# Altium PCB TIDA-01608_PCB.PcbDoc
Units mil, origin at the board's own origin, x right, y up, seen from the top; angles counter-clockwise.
Board outline 3040 x 2040 mil, 2 copper layers (Top Layer, Bottom Layer), stack 62 mil thick; 66 components, 23 nets, 147 pads, 82 vias.
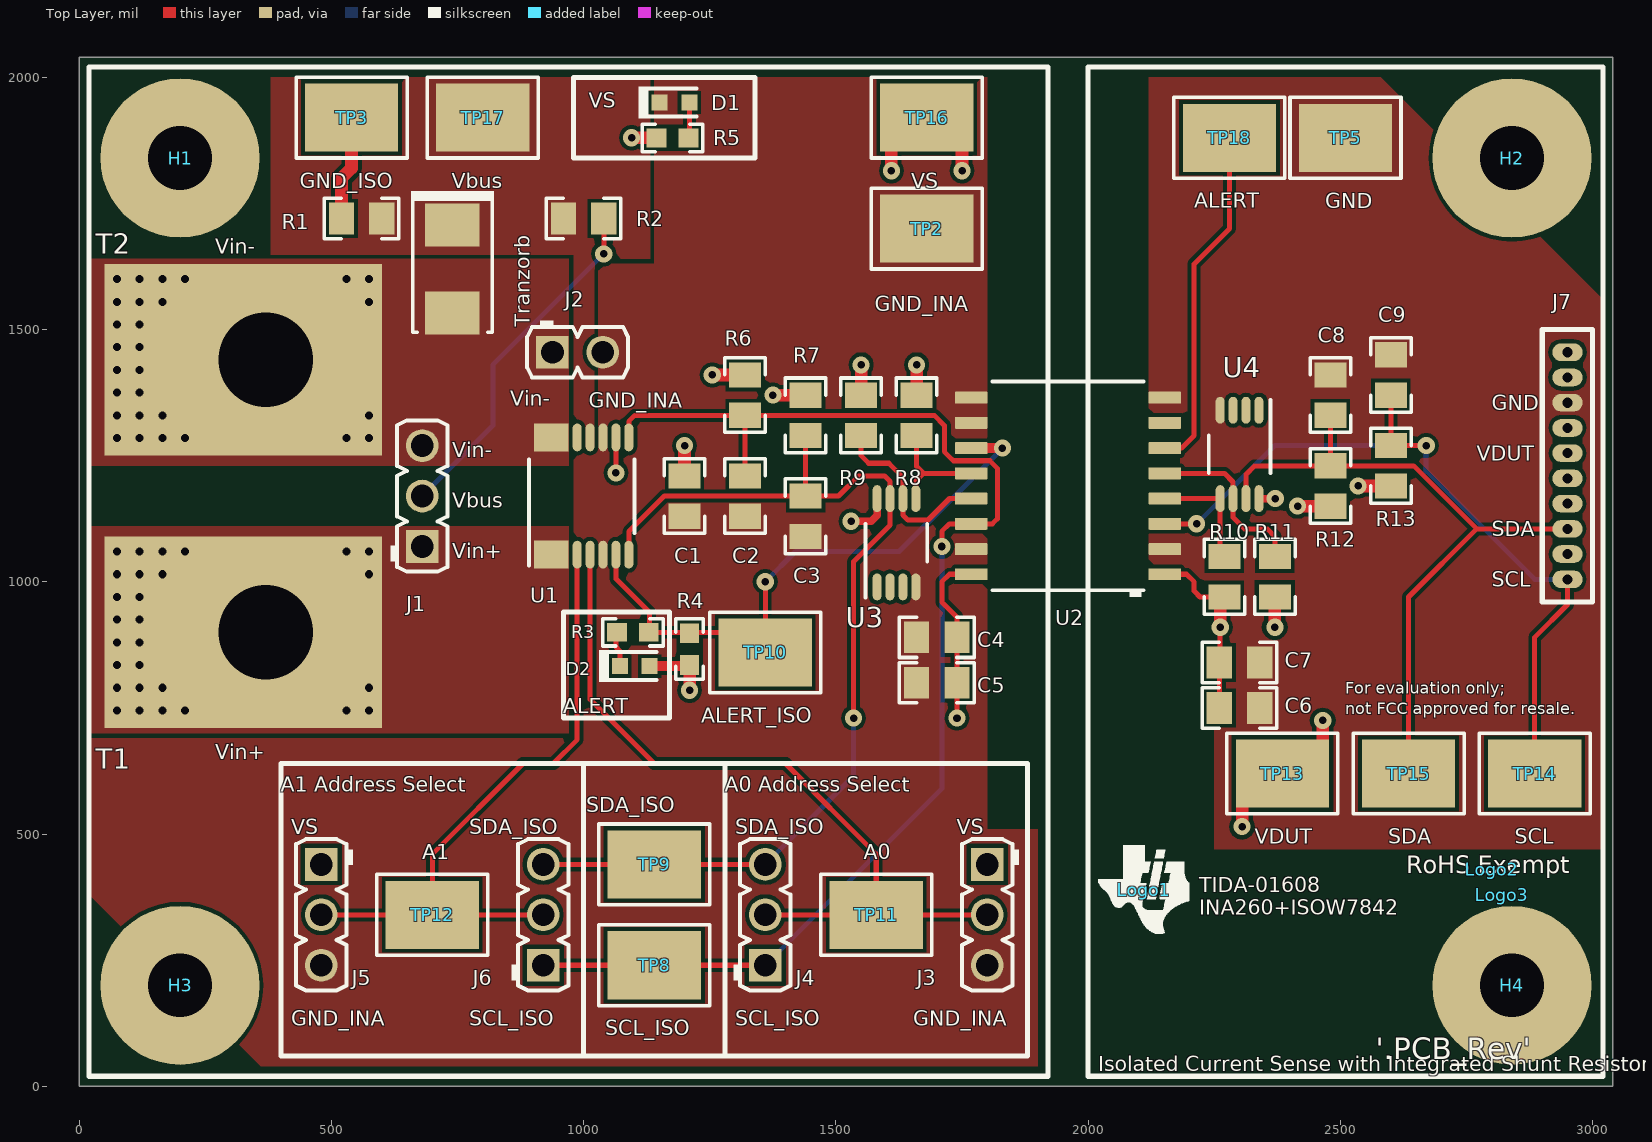
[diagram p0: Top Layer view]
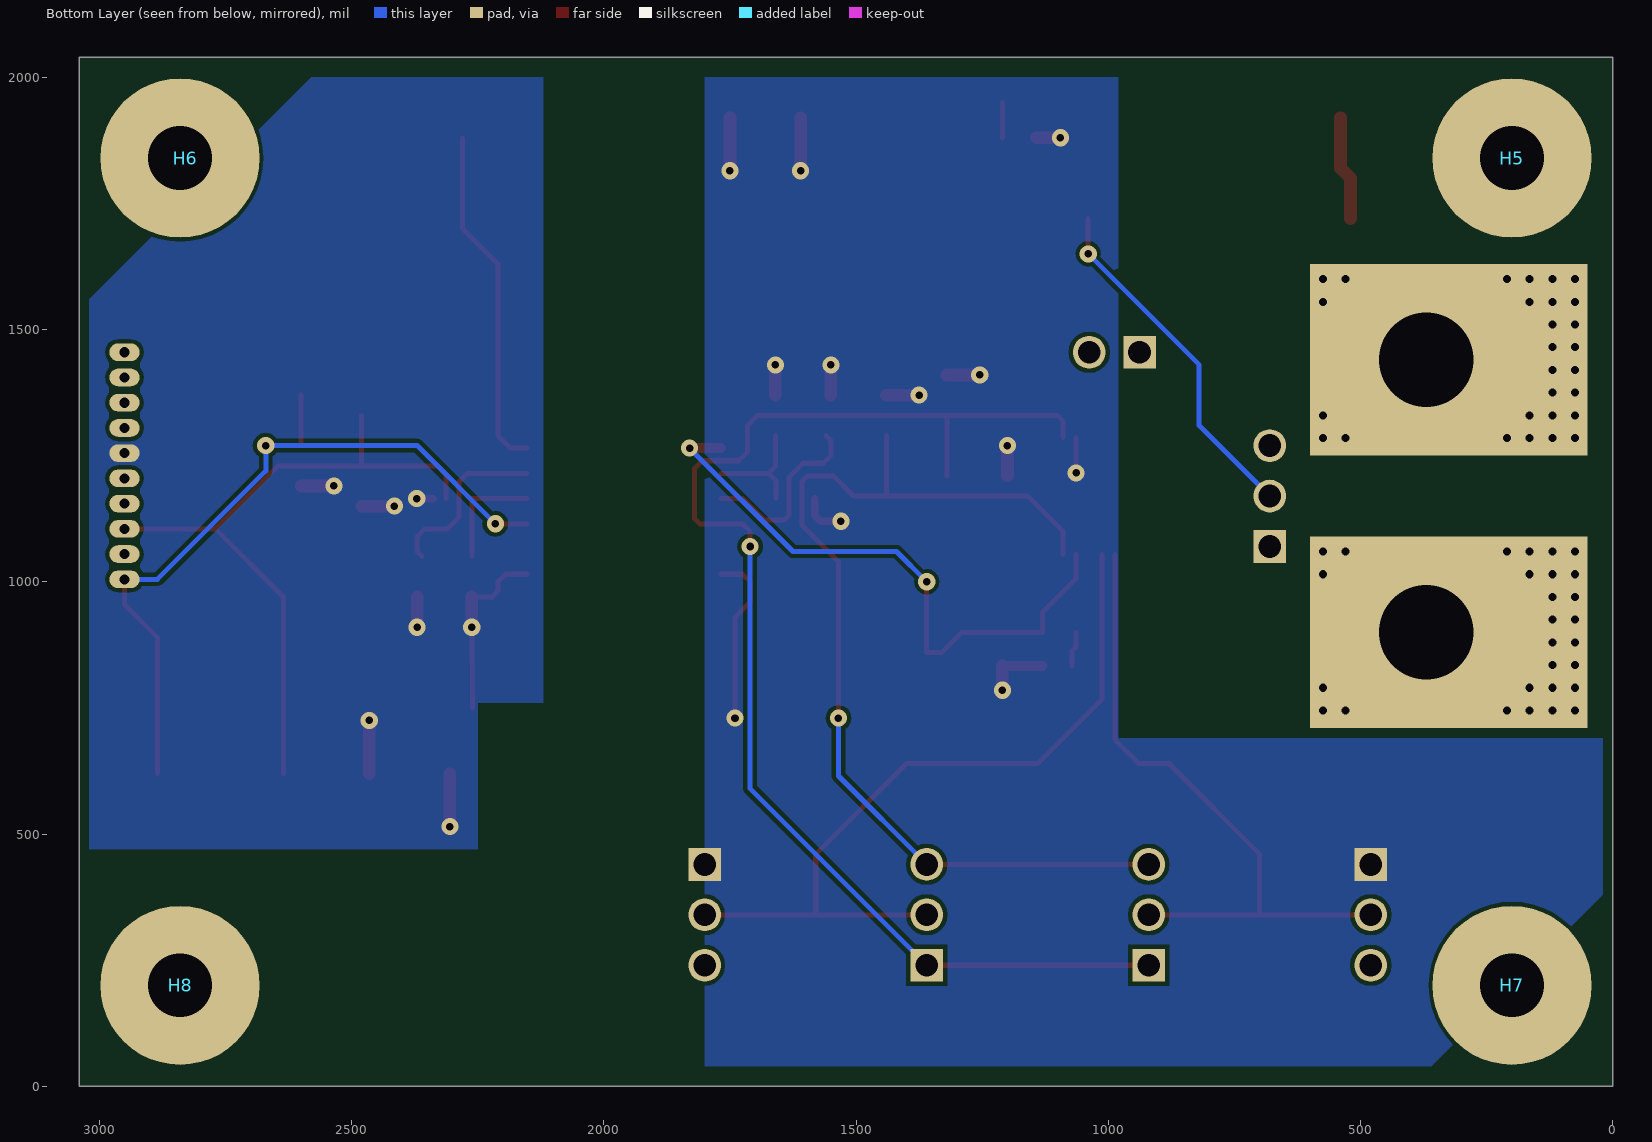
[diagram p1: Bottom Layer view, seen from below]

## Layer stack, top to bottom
Top Solder: solder mask 0.4, Solder Resist, Dk 3.5
Top Layer: signal copper 1.4
Dielectric1: core 59.2, FR-4, Dk 4.8
Bottom Layer: signal copper 1.4
Bottom Solder: solder mask 0.4, Solder Resist, Dk 3.5

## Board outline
0,0 0,2040 3040,2040 3040,0

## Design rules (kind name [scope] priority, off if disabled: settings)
AcuteAngle [All] p1: minimum=4.50000000000000E+0001 checktracksonly=FALSE
AssemblyTestPointUsage [All] p1: valid=2
Clearance Clearance_Keepouts [((IsTrack Or IsArc) And Not InPoly) And IsFree and IsKeepOut vs ((IsTrack Or IsArc) And Not InPoly) And IsFree and IsKeepOut] p1: gap=0 ignorepadtopadclearanceinfootprint=FALSE
Clearance Clearance_BoardEdge_MountingHoles [OnCopper and InComponentClass('Mounting Holes') vs IsKeepOut] p2: gap=40 ignorepadtopadclearanceinfootprint=FALSE except(0: Arc-Hole Track-Hole SMDPad-Hole THPad-Hole Via-Hole Fill-Hole Poly-Hole Region-Hole Text-Hole)
Clearance Clearance_BoardEdge_Poly [OnCopper and InPoly vs IsKeepOut] p3: gap=25 ignorepadtopadclearanceinfootprint=FALSE except(0: Arc-Hole Track-Hole SMDPad-Hole THPad-Hole Via-Hole Fill-Hole Poly-Hole Region-Hole Text-Hole)
Clearance Clearance_BoardEdge [OnCopper and Not InComponentClass('Logo') and not InComponentClass('FiducialMark') and not InRegion(1000,500,4000,800) and Not IsKeepout vs IsKeepOut] p4: gap=20 ignorepadtopadclearanceinfootprint=FALSE except(0: Arc-Hole Track-Hole SMDPad-Hole THPad-Hole Via-Hole Fill-Hole Poly-Hole Region-Hole Text-Hole)
Clearance Clearance_Poly [InPolygon] p5: gap=8 ignorepadtopadclearanceinfootprint=FALSE except(0: Arc-Hole Track-Hole SMDPad-Hole THPad-Hole Via-Hole Fill-Hole Poly-Hole Region-Hole Text-Hole)
Clearance [All] p6: gap=7 ignorepadtopadclearanceinfootprint=FALSE except(0: Arc-Hole Track-Hole SMDPad-Hole THPad-Hole Via-Hole Fill-Hole Poly-Hole Region-Hole Text-Hole)
ComponentClearance ComponentClearance_FCCLogo [InComponent('Logo3') vs InComponent('H4')] p1: gap=0 collisioncheckmode=3 verticalgap=0 showdistances=FALSE
ComponentClearance ComponentClearance_MountingHoles_FiducialMarks [InComponentClass('Mounting Holes') vs InComponentClass('FiducialMark')] p2: gap=7 collisioncheckmode=3 verticalgap=10 showdistances=FALSE
ComponentClearance ComponentClearance_Shunt [InComponentClass('Header') vs InComponentClass('Shunt')] p3: gap=0 collisioncheckmode=3 verticalgap=0 showdistances=FALSE
ComponentClearance ComponentClearance_Logo [InComponentClass('Logo')] p4: gap=0 collisioncheckmode=3 verticalgap=0 showdistances=FALSE
ComponentClearance ComponentClearance_ScrewToNut [(HasFootprint('NY PMS 440 0025 PH')) vs (HasFootprint('Keystone_1902C'))] p5: gap=5 collisioncheckmode=3 verticalgap=10 showdistances=FALSE
ComponentClearance ComponentClearance_MountingHoles [InComponentClass('Mounting Holes') vs InAnyComponent And Not InComponentClass('Hardware')] p6: gap=10 collisioncheckmode=3 verticalgap=10 showdistances=TRUE
ComponentClearance ComponentClearance_SmallPassives [HasFootprint('0201*') or HasFootprint('0402*') or HasFootprint('0508') or HasFootprint('0603*') or HasFootprint('0612') or HasFootprint('0805*') or HasFootprint('0815*') or HasFootprint('0830*') or HasFootprint('1206*') or HasFootprint('1210*') or HasFootprint('1808*') or HasFootprint('1812*') or HasFootprint('1825*') or HasFootprint('2010*') or HasFootprint('2220*') or HasFootprint('2225*') or HasFootprint('2512*') or HasFootprint('2728*') or HasFootprint('3518*') vs HasFootprint('0201*') or HasFootprint('0402*') or HasFootprint('0508') or HasFootprint('0603*') or HasFootprint('0612') or HasFootprint('0805*') or HasFootprint('0815*') or HasFootprint('0830*') or HasFootprint('1206*') or HasFootprint('1210*') or HasFootprint('1808*') or HasFootprint('1812*') or HasFootprint('1825*') or HasFootprint('2010*') or HasFootprint('2220*') or HasFootprint('2225*') or HasFootprint('2512*') or HasFootprint('2728*') or HasFootprint('3518*')] p7: gap=20 collisioncheckmode=3 verticalgap=10 showdistances=FALSE
ComponentClearance ComponentClearance_THtoSMT [IsThruComponent And  Not InComponentClass('Hardware') vs IsSMTComponent And  Not InComponentClass('Hardware')] p8: gap=10 collisioncheckmode=3 verticalgap=10 showdistances=FALSE
ComponentClearance ComponentClearance_THtoTH [IsThruComponent vs IsThruComponent] p9: gap=10 collisioncheckmode=3 verticalgap=10 showdistances=FALSE
ComponentClearance [Not InComponentClass('Hardware') And  Not InComponentClass('Logo') vs Not InComponentClass('Hardware') And  Not InComponentClass('Logo')] p10: gap=7 collisioncheckmode=3 verticalgap=7 showdistances=TRUE
DiffPairsRouting [All] p1: maxlimit=100 minlimit=10 mostfreqgap=10 toplayer_minwidth=15 toplayer_maxwidth=15 toplayer_prefwidth=15 bottomlayer_minwidth=15 bottomlayer_maxwidth=15 bottomlayer_prefwidth=15 maxuncoupledlength=1000
FabricationTestPointUsage TestPointUsage [All] p1: valid=2 allowmultiple=FALSE
FabricationTestpoint Testpoint [All] p1: side=3 testpointundercomponent=TRUE minsize=40 maxsize=100 preferedsize=60 minholesize=0 maxholesize=40 preferedholesize=32 testpointgrid=1 allowsidetop=TRUE allowsidebottom=TRUE usegrid=TRUE gridtolerance=0.01
FanoutControl Fanout_LCC [IsLCC] p1: bgadir=Out bgaviamode=Centered fanoutstyle=Auto fanoutdirection=Alternating viagrid=1 // Fanout_LCC (Default Rule)
FanoutControl Fanout_BGA [IsBGA] p2: bgadir=Out bgaviamode=Centered fanoutstyle=Auto fanoutdirection=Alternating viagrid=1 // Fanout_BGA (Default Rule)
FanoutControl Fanout_Default [All] p4: bgadir=Out bgaviamode=Centered fanoutstyle=Auto fanoutdirection=Alternating viagrid=1 // Fanout_Default (Default Rule)
FanoutControl Fanout_Small [(CompPinCount < 5)] p5: bgadir=Out bgaviamode=Centered fanoutstyle=Auto fanoutdirection=OutThenIn viagrid=1 // Fanout_Small (Default Rule)
Height [All] p1 off: minheight=0 maxheight=1000 prefheight=500
HoleSize [All] p1: absolutevalues=TRUE maxlimit=251 minlimit=8 maxpercent=80.000 minpercent=20.000
MinimumAnnularRing MinimumAnnularRing_ThermalPadVias [IsVia and InAnyComponent] p1: minimumring=5.91
MinimumAnnularRing [All] p2: minimumring=7
MinimumSolderMaskSliver MinimumSolderMaskSliver_Logo [InComponentClass('Logo') vs InComponentClass('Logo')] p1: minsoldermaskwidth=0.7
MinimumSolderMaskSliver [All] p2: minsoldermaskwidth=4
PlaneConnect [All] p1: planeconnectstyle=Relief reliefexpansion=10 reliefentries=4 reliefconductorwidth=10 reliefairgap=10
PolygonConnect [All] p1: connectstyle=Direct reliefconductorwidth=10 reliefentries=4 polygonreliefangle="90 Angle" airgapwidth=10
RoutingVias ThermalPadVias [IsVia and InAnyComponent] p1: holewidth=8 width=19.68 viastyle="Through Hole" minholewidth=7.87 minwidth=19.68 maxholewidth=999 maxwidth=999
RoutingVias [All] p2: holewidth=15 width=34 viastyle="Through Hole" minholewidth=8 minwidth=26 maxholewidth=999 maxwidth=999
SilkToSilkClearance SilkToSilkClearance_Pb-FreeLogo [(HasFootprint('Pb-Free_Overlay_Medium') OR HasFootprint('Pb-Free_Overlay_Small')) vs (HasFootprint('Pb-Free_Overlay_Medium') OR HasFootprint('Pb-Free_Overlay_Small'))] p1 off: silktosilkclearance=0
SilkToSilkClearance [All] p2 off: silktosilkclearance=3
SilkToSolderMaskClearance SilkToComonentPadClearance [IsPad and InAnycomponent vs Not InComponentClass('Hardware')] p1: minsilkscreentomaskgap=3 clearancetoexposedcopper=TRUE
SilkToSolderMaskClearance "Silk to Solder Mask Opening" [Not InComponentClass('Hardware') vs Not InComponentClass('Hardware')] p2: minsilkscreentomaskgap=3 clearancetoexposedcopper=FALSE
SolderMaskExpansion [All] p1: expansion=0
Width [All] p1: maxlimit=100 minlimit=6 preferedwidth=10 checkconnectedcopper=TRUE
15 further rules are at their usual default settings.

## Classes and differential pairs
component class AssemblyNote: ZZ2 ZZ3 ZZ4
component class Header: J1 J2 J3 J4 J5 J6
component class TIDA-01608_SCH: C1 C2 C3 C4 C5 C6 C7 C8 C9 D1 D2 D3 J1 J2 J3 J4 J5 J6 J7 R1 R2 R3 R4 R5 R6 R7 R8 R9 R10 R11 R12 R13 T1 T2 TP2 TP3 TP5 TP8 TP9 TP10 TP11 TP12 TP13 TP14 TP15 TP16 TP17 TP18 Tranzorb U1 U2 U3 U4
component class "Mounting Holes": H1 H2 H3 H4
component class Logo: Logo1
component class TIDA-01608_HW: H1 H2 H3 H4 H5 H6 H7 H8 Logo1 Logo2 Logo3 ZZ2 ZZ3 ZZ4

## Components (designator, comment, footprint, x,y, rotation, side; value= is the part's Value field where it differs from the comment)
C1 "08055C104KAT2A" 0805_HV 1200,1170 r270 top value=0.1uF
C2 "08051A330JAT2A" 0805_HV 1320,1170 r270 top value=33pF
C3 "08051A330JAT2A" 0805_HV 1440,1130 r270 top value=33pF
C4 "GRM21BR61A226ME44L" 0805_HV 1700,890 r0 top value=22uF
C5 "08055C104KAT2A" 0805_HV 1700,800 r180 top value=0.1uF
C6 "08055C104KAT2A" 0805_HV 2300,750 r0 top value=0.1uF
C7 "GRM21BR61A226ME44L" 0805_HV 2300,840 r180 top value=22uF
C8 "08051A330JAT2A" 0805_HV 2480,1370 r90 top value=33pF
C9 "08051A330JAT2A" 0805_HV 2600,1410 r90 top value=33pF
D1 "LTST-C190GKT" LED_LTST-C190 1180,1950 r180 top value=Green
D2 "LTST-C190CKT" LED_LTST-C190_Red 1101.38,833.07 r180 top value=Red
H1 "NY PMS 440 0025 PH" "NY PMS 440 0025 PH"#1 200,1840 r0 top locked
H2 "NY PMS 440 0025 PH" "NY PMS 440 0025 PH"#2 2830,1840 r0 top locked
H3 "NY PMS 440 0025 PH" "NY PMS 440 0025 PH"#1 200,200 r0 top locked
H4 "NY PMS 440 0025 PH" "NY PMS 440 0025 PH"#1 2840,200 r0 top locked
H5 "1902C" Keystone_1902C 200,1840 r180 bottom locked
H6 "1902C" Keystone_1902C 2830,1840 r180 bottom locked
H7 "1902C" Keystone_1902C 200,200 r180 bottom locked
H8 "1902C" Keystone_1902C 2840,200 r180 bottom locked
J1 "61300311121" WURTH_61300311121 680,1170 r90 top
J2 "61300211121" WURTH_61300211121 988,1455 r0 top
J3 "61300311121" WURTH_61300311121 1800,340 r270 top
J4 "61300311121" WURTH_61300311121 1360,340 r90 top
J5 "61300311121" WURTH_61300311121 480,340 r270 top
J6 "61300311121" WURTH_61300311121 920,340 r90 top
J7 "851-43-010-20-001000" 851-43-010-20-001000 2950,1230 r180 top
Logo1 "Texas Instruments" TI_Symbol_Overlay_Small 2110,390 r0 top
Logo2 "EU RoHS Exempt Logo" EURoHS_Exempt_60mil 2800,430 r0 top
Logo3 "FCC disclaimer" FCC_disclaimer_stacked 2820,380 r0 top
R1 "CRCW080535K7FKEA" 0805_HV 560,1720 r180 top value=35.7k
R2 "CRCW080512K1FKEA" 0805_HV 1000,1720 r180 top value=12.1k
R3 "RC0603JR-07910RL" 0603 1097.44,900 r0 top value=910
R4 "ERJ-3EKF1002V" 0603 1210,866.54 r90 top value=10.0k
R5 "RC0603JR-07910RL" 0603 1176.06,1880 r180 top value=910
R6 "CRCW080510K0FKEA" 0805_HV 1320,1370 r90 top value=10.0k
R7 "CRCW080510K0FKEA" 0805_HV 1440,1330 r90 top value=10.0k
R8 "CRCW080510K0FKEA" 0805_HV 1660,1330 r90 top value=10.0k
R9 "CRCW080510K0FKEA" 0805_HV 1550,1330 r90 top value=10.0k
R10 "CRCW080510K0FKEA" 0805_HV 2270,1010 r270 top value=10.0k
R11 "CRCW080510K0FKEA" 0805_HV 2370,1010 r270 top value=10.0k
R12 "CRCW080510K0FKEA" 0805_HV 2480,1190 r270 top value=10.0k
R13 "CRCW080510K0FKEA" 0805_HV 2600,1230 r270 top value=10.0k
T1 "CB35-36-CY" CB35-36-CY 370,900 r0 top
T2 "CB35-36-CY" CB35-36-CY 370,1440 r0 top
TP2 "GND_INA" Testpoint_Keystone_Compact 1680,1700 r0 top value=SMT
TP3 "GND_ISO" Testpoint_Keystone_Compact 540,1920 r180 top value=SMT
TP5 "GND" Testpoint_Keystone_Compact 2510,1880 r0 top value=SMT
TP8 "SCL_ISO" Testpoint_Keystone_Compact 1140,240 r0 top value=SMT
TP9 "SDA_ISO" Testpoint_Keystone_Compact 1140,440 r0 top value=SMT
TP10 "ALERT_ISO" Testpoint_Keystone_Compact 1360,860 r180 top value=SMT
TP11 "A0" Testpoint_Keystone_Compact 1580,340 r180 top value=SMT
TP12 "A1" Testpoint_Keystone_Compact 700,340 r180 top value=SMT
TP13 "VDUT" Testpoint_Keystone_Compact 2385,620 r0 top value=SMT
TP14 "SCL" Testpoint_Keystone_Compact 2885,620 r0 top value=SMT
TP15 "SDA" Testpoint_Keystone_Compact 2635,620 r0 top value=SMT
TP16 "VS" Testpoint_Keystone_Compact 1680,1920 r180 top value=SMT
TP17 "Vbus" Testpoint_Keystone_Compact 800,1920 r180 top value=SMT
TP18 "ALERT" Testpoint_Keystone_Compact 2280,1880 r0 top value=SMT
Tranzorb "SMBJ30A-13-F" SMB 740,1620 r270 top value=24V
U1 "INA260AIPWR" PW0016A_N 1000,1170 r90 top
U2 "ISOW7842DWER" DWE0016A 1960,1190 r180 top
U3 "P82B96DGKR" DGK0008A_N 1620,1077.4 r90 top
U4 "P82B96DGKR" DGK0008A_N 2300,1252.6 r270 top
ZZ2 "These assemblies are ESD sensitive, ESD precautions shall be observed." AssemblyNote 320,2810 r0 top
ZZ3 "These assemblies must be clean and free from flux and all contaminants. Use of no clean flux is not acceptable." AssemblyNote 320,2640 r0 top
ZZ4 "These assemblies must comply with workmanship standards IPC-A-610 Class 2, unless otherwise specified." AssemblyNote 320,2440 r0 top

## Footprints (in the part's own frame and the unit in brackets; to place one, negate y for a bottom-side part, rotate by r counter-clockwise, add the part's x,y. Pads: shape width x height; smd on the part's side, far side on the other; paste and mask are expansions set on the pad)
0603 [mm] "0603 from SM-752 data"
  rect 1x0.95 smd: 1(-0.8,0) 2(0.8,0)
  silkscreen extent -1.52,-0.69 1.52,0.69, body extent -0.87,-0.47 0.87,0.47, height 1
0805_HV [mil] "0805 with 30mil clearance between pads"
  rect 50x63 smd: 1(-40,0) 2(40,0)
  silkscreen extent -74,-40 74,40, body extent -43,-29 43,29, height 43
851-43-010-20-001000 [mil] "Female 10 Pin connector for SM-USB-DIG"
  oval 60x35 hole 20: 1(0,225) 2(0,175) 3(0,125) 4(0,75) 5(0,25) 6(0,-25) 7(0,-75) 8(0,-125) 9(0,-175) 10(0,-225)
  silkscreen extent -50,-270 50,270, body extent -210,-257 8,257, height 87
AssemblyNote [mil] "Assembly Note"
CB35-36-CY [mil] "Terminal 50A Lug"
  rect 550x380 hole 188 copper offset -45,0 paste-190: 1(0,0)
  body extent -960,-189 230,191, height 614
DGK0008A_N [mm] "TSOP, 8-Leads, Body 3x3mm, Pitch 0.65mm, IPC Medium Density"
  oval 1.35x0.45 smd: 1(-2.225,0.975) 2(-2.225,0.325) 3(-2.225,-0.325) 4(-2.225,-0.975) 5(2.225,-0.975) 6(2.225,-0.325) 7(2.225,0.325) 8(2.225,0.975)
  silkscreen extent -2.75,-1.55 0.95,1.55, body extent -2.45,-1.5 2.45,1.5, height 0.96
DWE0016A [mm] "SOIC, 16-Leads, Body 10.5x7.6mm, Pitch 1.27mm"
  rrect17% 1.65x0.6 smd: 1(-4.875,4.445) 2(-4.875,3.175) 3(-4.875,1.905) 4(-4.875,0.635) 5(-4.875,-0.635) 6(-4.875,-1.905) 7(-4.875,-3.175) 8(-4.875,-4.445) 9(4.875,-4.445) 10(4.875,-3.175) 11(4.875,-1.905) 12(4.875,-0.635) 13(4.875,0.635) 14(4.875,1.905) 15(4.875,3.175) 16(4.875,4.445)
  silkscreen extent -3.8,-5.25 3.8,5.6, body extent -5.17,-5.15 5.17,5.15, height 2.59
EURoHS_Exempt_60mil [mil] "EU RoHS Exempt symbol"
FCC_disclaimer_stacked [mil]
Keystone_1902C [mil] "Hex Standoff, 4-40 threaded, nylon"
  body extent -145,-126 146,126, height 501
LED_LTST-C190 [mm] "Lite-On"
  rect 0.8x0.8 smd: 1(-0.75,0) 2(0.75,0)
  silkscreen extent -1.1,-0.8 1.8,0.8, body extent -0.85,-0.45 0.85,0.45, height 0.9
LED_LTST-C190_Red [mm] "Lite-On"
  rect 0.8x0.8 smd: 1(-0.75,0) 2(0.75,0)
  silkscreen extent -1.1,-0.8 1.8,0.8, body extent -0.85,-0.45 0.85,0.45, height 0.9
"NY PMS 440 0025 PH"#1 [mm] "4-40 nylon screw and mounting hole"
  round 8 hole 3.2: 1(0,0)
  body extent -3.3,-3.3 3.3,3.3, height 2.69
"NY PMS 440 0025 PH"#2 [mm] "4-40 nylon screw and mounting hole"
  round 8 hole 3.2: 1(0.254,0)
  body extent -3.3,-3.3 3.3,3.3, height 2.69
PW0016A_N [mm] "TSOP, 16-Leads, Body 5x4.4mm, Pitch 0.65mm, IPC Medium Density"
  oval 1.4x0.45 smd: 1(-2.95,2.275) 2(-2.95,1.625) 3(-2.95,0.975) 4(-2.95,0.325) 5(-2.95,-0.325) 6(-2.95,-0.975) 7(-2.95,-1.625) 8(-2.95,-2.275) 9(2.95,-2.275) 10(2.95,-1.625) 11(2.95,-0.975) 12(2.95,-0.325) 13(2.95,0.325) 14(2.95,0.975) 15(2.95,1.625) 16(2.95,2.275)
  silkscreen extent -3.5,-2.55 1.85,2.75, body extent -3.21,-2.5 3.21,2.5, height 1
SMB [mil] "Molded Diode, 2-Leads, Body 5.4x3.6mm, IPC Medium Density, based on OnSemi component dimensions"
  rect 85x107.99 smd: 1(-87.01,0) 2(87.01,0)
  silkscreen extent -155,-82 125,82, body extent -106,-71 106,71, height 91
Testpoint_Keystone_Compact [mil] "Compact SMT test point"
  rect 185x135 smd: 1(0,0)
  silkscreen extent -110,-80 110,80, body extent -75,-56 75,56, height 91
TI_Symbol_Overlay_Small [mil]
  silkscreen extent -90,-88 91,88
WURTH_61300211121 [mm] "Header, 2.54mm, 2x1, TH"
  rect 1.65x1.65 hole 1.15: 1(-1.27,0)
  round 1.65 hole 1.15: 2(1.27,0)
  silkscreen extent -2.54,-1.27 2.54,1.6, body extent -2.54,-1.27 2.54,1.27, height 8.54
WURTH_61300311121 [mm] "Header, 2.54mm, 3x1, TH"
  rect 1.65x1.65 hole 1.15: 1(-2.54,0)
  round 1.65 hole 1.15: 2(0,0) 3(2.54,0)
  silkscreen extent -3.81,-1.27 3.81,1.6, body extent -3.81,-1.27 3.81,1.27, height 8.54

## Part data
C1 C5 C6: "CAP, CERM, 0.1uF, 50V, +/-10%, X7R, 0805", Cap_Case=0805, Manufacturer=AVX, Supplier Part Number 1=478-1395-1-ND, TempCo=X7R, Tolerance_%=10, Value1="0.024 ohm", Value2=50V, ValueDisplayed=0.1µF
C2 C3 C8 C9: "CAP, CERM, 33 pF, 100 V,+/- 5%, C0G/NP0, 0805", Cap_Case=0805, Manufacturer=AVX, Supplier Part Number 1=478-1281-1-ND, TempCo=C0G/NP0, Tolerance_%=5, Value1="0.708 ohm", Value2=100V, ValueDisplayed=33pF
C4 C7: library part CMP-0008286-2, "CAP, CERM, 22 uF, 10 V, +/- 20%, X5R, 0805", Cap_Case=0805, Manufacturer=MuRata, Supplier Part Number 1=490-10746-1-ND, TempCo=X5R, Tolerance_%=20%, Value1=Unknown, Value2=10V, ValueDisplayed=22uF
D1: "LED, Green, SMD", Color=green, Manufacturer=Lite-On, Power_TotalModule=0.1, Supplier Part Number 1=160-1183-1-ND, Value1=0.1W, Value2=2.1V
D2: "LED, Red, SMD", Color=red, Manufacturer=Lite-On, Power_TotalModule=0.0625, Supplier Part Number 1=160-1181-1-ND, Value1=0.0625W, Value2=2V
H1 H2 H3 H4: "Machine Screw, Round, #4-40 x 1/4, Nylon, Philips panhead", Alternate Manufacturer=-, DigiKeyPartNumber=H542-ND, Manufacturer="B&F Fastener Supply"
H5 H6 H7 H8: "Standoff, Hex, 0.5\"L #4-40 Nylon", Alternate Manufacturer=-, Manufacturer=Keystone, Supplier Part Number 1=1902CK-ND
J1 J3 J4 J5 J6: library part CMP-0054796-1, "Header, 2.54 mm, 3x1, Gold, TH", Manufacturer="Wurth Elektronik", Supplier Part Number 1=732-5316-ND
J2: "Header, 2.54 mm, 2x1, Gold, TH", Manufacturer="Wurth Elektronik", Supplier Part Number 1=732-5315-ND
J7: library part SM-USB-DIG-CONN, "10-Pin 50-mil Connector of SM-USB-DIG", Alternate Manufacturer=-, Manufacturer="Mill-Max Manufacturing Corp."
Logo1: library part TI_Logo, "Texas Instrument Corporate Signature"
Logo2: library part EURoHS_Exempt
Logo3: library part FCC_disclaimer, "FCC_disclaimer"
R1: "RES, 35.7k ohm, 1%, 0.125W, 0805", Manufacturer=Vishay-Dale, Power_W=0.125, Supplier Part Number 1=541-35.7KCCT-ND, TempCo="100 ppm/C", Tolerance_%=1, Value1=1%, Value2=0.125W, Value_Code=35k7
R2: "RES, 12.1k ohm, 1%, 0.125W, 0805", Manufacturer=Vishay-Dale, Power_W=0.125, Supplier Part Number 1=541-12.1KCCT-ND, TempCo="100 ppm/C", Tolerance_%=1, Value1=1%, Value2=0.125W, Value_Code=12k1
R3 R5: library part CMP-0025943-2, "RES, 910, 5%, 0.1 W, 0603", Manufacturer="Yageo America", Power_W=100mW, Supplier Part Number 1=311-910GRCT-ND, TempCo="100 ppm/C", Tolerance_%=5%, Value2=0.1W, Value_Code=910R, ValueDisplayed=910
R4: library part CMP-0022684-2, "RES, 10.0 k, 1%, 0.1 W, 0603", Manufacturer=Panasonic, Power_W=100mW, Supplier Part Number 1=P10.0KHCT-ND, TempCo="100 ppm/C", Tolerance_%=1%, Value2=0.1W, Value_Code=10k0, ValueDisplayed=10.0k
R6 R7 R8 R9 R10 R11 R12 R13: "RES, 10.0 k, 1%, 0.125 W, 0805", Manufacturer=Vishay-Dale, Power_W=0.125, Supplier Part Number 1=541-10.0KCCT-ND, TempCo="100 ppm/C", Tolerance_%=1, Value1=1%, Value2=0.125W, Value_Code=10k0, ValueDisplayed=10.0k
T1 T2: "Terminal 50A Lug", Manufacturer=Panduit, Supplier Part Number 1=CB35-36-CY-ND, Voltage_V=600
TP2 TP3 TP5 TP8 TP9 TP10 TP11 TP12 TP13 TP14 TP15 TP16 TP17 TP18: library part 5016, "Test Point, Compact, SMT", Manufacturer=Keystone, Supplier Part Number 1=5016KCT-ND
Tranzorb: library part SMBJ24A-13-F, "Diode, TVS, Uni, 24V, 600W, SMB", Manufacturer="Diodes Inc.", Power_W=5, Supplier Part Number 1=SMBJ24A-FDICT-ND, Value1=5W
U1: "High/Low-Side Digital Current/Power Monitor with Integrated 2mO Shunt Resistor, PW0016A (TSSOP-16)", Alternate Manufacturer="Texas Instruments", Alternate PartNumber=INA260AIPW
U2: "High-Performance, 5000-VRMS Reinforced Quad-Channel Digital Isolators With Integrated High-Efficiency, Low-Emissions DC-DC Converter, DWE0016A (SOIC-16)", Alternate Manufacturer="Texas Instruments", Alternate PartNumber=ISOW7842DWE
U3 U4: "Dual Bidirectional Bus Buffer, 2 Channel Width, 2.0 to 15.0 V, -40 to 85 degC, 8-pin MSOP (DGK), Green (RoHS & no Sb/Br)", 5V Tolerant I/O=Yes, Alternate Manufacturer="Texas Instruments", Alternate PartNumber=Equivalent, Master Side I2C Bus Capacitance Supported(pF)=400, Supplier Part Number 1=296-20941-2-ND
ZZ2: library part CMP-0077236-1
ZZ3: library part CMP-0077237-1
ZZ4: library part CMP-0077238-1

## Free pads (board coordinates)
  rect 68.9x55.12 smd: 1(936.02,1053.86) 1(936.02,1286.14)

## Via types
v1: diameter 32, hole 16, Top Layer to Bottom Layer, 56 vias
v2: diameter 34, hole 15, Top Layer to Bottom Layer, 26 vias

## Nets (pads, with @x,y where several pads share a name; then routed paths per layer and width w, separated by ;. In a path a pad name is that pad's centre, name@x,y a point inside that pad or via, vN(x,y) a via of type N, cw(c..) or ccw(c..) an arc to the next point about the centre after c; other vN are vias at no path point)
A0: J3.2 J4.2 TP11.1 U1.5 | length 1541.1
  Top Layer w10: U1.5 1012.8,767.2 1140,640 1400,640 1580,460 TP11.1 ; J4.2 TP11.1 ; J3.2 TP11.1
A1: J5.2 J6.2 TP12.1 U1.4 | length 1308
  Top Layer w10: J5.2 TP12.1 ; J6.2 TP12.1 ; U1.4 987.2,687.2 940,640 880,640 700,460 TP12.1
ALERT: TP18.1 U2.6 | length 687.4
  Top Layer w10: U2.6 2185,1265 2210,1290 2210,1630 2280,1700 TP18.1
ALERT_ISO: R3.2 R4.2 TP10.1 U1.7 U2.11 | length 1208.9
  Top Layer w10: U1.7 1063.98,1006.02 1130.91,939.09 1130.91,900 1210,900 1290,900 1330,860 TP10.1 v2(1360,1000)
  Top Layer w20: U2.11 v2(1830,1265)
  Bottom Layer w10: v2(1360,1000) 1420,1060 1625,1060 v2(1830,1265)
GND: C6.2 C7.1 C8.2 C9.2 J7.8 TP5.1 U2.2 U2.8 U4.4
GND_INA: C1.2 C2.2 C3.2 C4.1 C5.2 D1.2 J2.2 J3.3 J5.3 TP2.1 U1.6 U1.11 U2.9 U2.10 U2.15 U3.4
GND_ISO: R1.2 TP3.1 | length 208.3
  Top Layer w25: R1.2 520,1800 540,1820 TP3.1
NetD1_1: D1.1 R5.1 | length 70
  Top Layer w10: R5.1@1209.52,1880 D1.1
NetD2_2: D2.2 R3.1 | length 70.2
  Top Layer w10: R3.1@1063.98,900 1063.98,871.02 1071.85,863.15 D2.2
NetJ1_2: J1.2 R2.1 | length 699.1
  Top Layer w10: v2(1040,1650) R2.1
  Bottom Layer w10: J1.2 820,1310 820,1430 v2(1040,1650)
NetR8_1: R8.1 U2.12 U3.5 | length 231.4
  Top Layer w10: U3.5 1658.39,1199.8 1673.58,1215 ; R8.1 1660,1228.58 1673.58,1215 ; U2.12 1673.58,1215
NetR9_1: R9.1 U2.13 U3.6 | length 376.6
  Top Layer w10: R9.1@1560,1290 1550,1280 1550,1250 1565,1235 1605,1235 1632.8,1207.2 U3.6 1632.8,1132.2 1642.5,1122.5 1682.5,1122.5 1725,1165 U2.13
NetR10_1: R10.1 U2.4 U4.5 | length 224.7
  Top Layer w10: U2.4 U4.5 R10.1@2261.61,1050
NetR11_1: R11.1 U2.5 U4.6 | length 355
  Top Layer w10: U2.5 2270,1215 2287.2,1197.8 U4.6 2287.2,1127.8 2310,1105 2355,1105 2370,1090 2370,1060 R11.1@2360,1050
SCL: C9.1 J7.1 R13.1 TP14.1 U2.3 | length 1583.3
  Top Layer w10: U2.3 v2(2215,1115) ; C9.1 R13.1 v2(2670,1270) ; TP14.1 2885,890 2950,955 J7.1
  Bottom Layer w10: v2(2215,1115) 2370,1270 v2(2670,1270) 2670,1220 2885,1005 J7.1
SCL_ISO: C2.1 J4.1 J6.1 R6.1 TP8.1 U1.9 U2.14 | length 2636.6
  Top Layer w10: J6.1 TP8.1 J4.1 ; U1.9 1089.57,1318.11 1101.46,1330 R6.1 ; C2.1 R6.1 ; v2@1700,1070 v2(1710,1070) 1710,1100 1725,1115 U2.14 1810,1115 1820,1125 1820,1225 1805,1240 1733.59,1240 1732.4,1241.19 1731.8,1241.19 1715,1257.99 1715,1310 1695,1330 R6.1
  Bottom Layer w10: J4.1 1710,590 v2(1710,1070)
SDA: C8.1 J7.3 R12.1 TP15.1 U4.7 | length 1384.8
  Top Layer w10: U4.7 2312.8,1212.8 2330,1230 R12.1 ; C8.1 R12.1 ; TP15.1 2635,970 2770,1105 ; J7.3 2770,1105 ; R12.1 2645,1230 2770,1105
SDA_ISO: C3.1 J4.3 J6.3 R7.1 TP9.1 U1.8 U3.7 | length 2035.2
  Top Layer w10: J6.3 TP9.1 J4.3 ; U1.8 1089.57,1099.57 1160,1170 C3.1 ; R7.1 C3.1 ; v2(1535,730) 1535,1040 1607.2,1112.2 U3.7 1607.2,1199.21 1596.42,1210 1545,1210 1505,1170 C3.1
  Bottom Layer w10: J4.3 1535,615 v2(1535,730)
VBUS: R1.1 R2.2 TP17.1 Tranzorb.1 U1.12
VDUT: C6.1 C7.2 J7.6 R10.2 R11.2 R12.2 R13.2 TP13.1 U2.1 U4.8 | length 790.2
  Top Layer w10: U2.1 2195,1015 2210,1000 2210,981.61 2221.61,970 R10.2@2261.61,970 ; C6.1 C7.2 ; C7.2@2261.61,841.61 v2(2261.61,910)
  Top Layer w15: U4.8 v2(2370.87,1165)
  Top Layer w25: v2(2261.61,910) R10.2@2261.61,970 ; v2(2305,514.73) TP13.1@2305,619.87 ; v2(2370,910) R11.2 ; v2(2415,1150) R12.2 ; TP13.1@2465,620.13 v2(2465,725.27) ; v2(2535,1190) R13.2
Vin+: J1.1 pad.1@936.02,1053.86 T1.1 U1.1 U1.2 U1.3
  other v1: 75,745 120,745 165,745 210,745 530,745 575,745 75,790 120,790 165,790 575,790 75,835 120,835 75,880 120,880 75,925 120,925 75,970 120,970 75,1015 120,1015 165,1015 575,1015 75,1060 120,1060 165,1060 210,1060 530,1060 575,1060
Vin-: J1.3 J2.1 pad.1@936.02,1286.14 T2.1 Tranzorb.2 U1.14 U1.15 U1.16
  other v1: 75,1285 120,1285 165,1285 210,1285 530,1285 575,1285 75,1330 120,1330 165,1330 575,1330 75,1375 120,1375 75,1420 120,1420 75,1465 120,1465 75,1510 120,1510 75,1555 120,1555 165,1555 575,1555 75,1600 120,1600 165,1600 210,1600 530,1600 575,1600
VS: C1.1 C4.2 C5.1 D2.1 J3.1 J5.1 R4.1 R5.2 R6.2 R7.2 R8.2 R9.2 TP16.1 U1.10 U2.16 U3.8 | length 1201.7
  Top Layer w10: v2(1063.98,1216.02) U1.10 ; v2(1740,730) C4.2 1740,930 1710,960 1710,1000 1725,1015 U2.16
  Top Layer w15: v2(1530,1120) 1570,1120 1581.61,1131.61 U3.8
  Top Layer w20: D2.1 R4.1@1210,833.07
  Top Layer w25: v2(1095,1880) R5.2@1142.6,1880 ; C1.1 v2(1200,1270) ; v2(1210,785) R4.1@1210,833.07 ; v2(1255,1410) R6.2 ; v2(1375,1370) R7.2 ; R9.2 v2(1550,1430) ; v2(1610,1814.87) TP16.1@1610,1920 ; R8.2 v2(1660,1430) ; v2(1750,1814.87) TP16.1@1750,1920
pads on no net: H1.1 H2.1 H3.1 H4.1 J7.2 J7.4 J7.5 J7.7 J7.9 J7.10 U1.13 U2.7 U3.1 U3.2 U3.3 U4.1 U4.2 U4.3

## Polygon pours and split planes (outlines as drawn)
GND on Top Layer "GND_L01_P035" (solid, remove dead copper, pour order 35): 2120,2000 2120,760 2250,760 2250,470 3020,470 3020,1560 2580,2000
GND_INA on Top Layer "GND_INA_L01_P033" (solid, remove dead copper, pour order 33): 1800,2000 1800,510 1900,510 1900,40 360,40 20,380 20,690 980,690 980,1320 1029,1320 1029,1630 1140,1630 1140,2000
Vin+ on Top Layer "VIN+_L01_P031" (solid, remove dead copper, pour order 31): 20,1110 970.47,1110 970.47,700 20,700
Vin- on Top Layer "VIN-_L01_P032" (solid, remove dead copper, pour order 32): 20,1640 970.47,1640 970.47,1230 20,1230
VBUS on Top Layer "VBUS_L01_P034" (solid, remove dead copper, pour order 34): 380,2000 380,1648 980,1648 980,1254.94 1022,1254.94 1022,1640 1135,1640 1135,2000
VS on Bottom Layer "VS_L02_P036" (solid, remove dead copper, pour order 36): 1800,2000 1800,40 360,40 20,380 20,690 980,690 980,2000
VDUT on Bottom Layer "VDUT_L02_P037" (solid, remove dead copper, pour order 37): 2120,2000 2120,760 2250,760 2250,470 3020,470 3020,1560 2580,2000

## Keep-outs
Keep-Out Layer:
  text ".Layer_Name" at 577,-1248.49 h30

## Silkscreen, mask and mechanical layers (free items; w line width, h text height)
Top Overlay:
  lines w10: 1000,60 1000,640 ; 1280,60 1280,640 ; 20,20 20,2020 1920,2020 1920,20 20,20 ; 400,60 1880,60 1880,640 400,640 400,60 ; 960,730 1170,730 1170,940 960,940 960,730 ; 980,1840 980,2000 1340,2000 1340,1840 980,1840 ; 2000,20 3020,20 3020,2020 2000,2020 2000,20
  text "VS" at 1010,1940 h30
  text "Vin-" at 270,1650 h30
  text "Vin-" at 855,1349 h30
  text "GND_INA" at 1010,1345 h30
  text "GND" at 2800,1340 h30
  text "Vin-" at 740,1247 h30
  text "VDUT" at 2770.01,1240 h30
  text "Vbus" at 740,1147 h30
  text "SDA" at 2800,1090 h30
  text "Vin+" at 740,1047 h30
  text "SCL" at 2800,990 h30
  text "ALERT" at 960,740 h30
  text "Vin+" at 270,648.01 h30
  text "A1 Address Select" at 400,584 h30
  text "A0 Address Select" at 1280,584 h30
  text "VS" at 420,500 h30
  text "SDA_ISO" at 773.06,500 h30
  text "SDA_ISO" at 1300,500 h30
  text "VS" at 1740,500 h30
  text "TIDA-01608 / INA260+ISOW7842" at 2220,340 h30
  text "GND_INA" at 420,120 h30
  text "SCL_ISO" at 773.06,120 h30
  text "SCL_ISO" at 1300,120 h30
  text "GND_INA" at 1653.06,120 h30
  text "'.PCB_Rev'" at 2570,40 h72.83
  text "Isolated Current Sense with Integrated Shunt Resistor and I2C Interface Reference Design" at 2020,30 h30
Bottom Paste:
  text ".Layer_Name" at 577,-1248.49 h30
Bottom Solder:
  text ".Layer_Name" at 577,-1248.49 h30
Drill Guide:
  text ".Layer_Name" at 577,-1248.49 h30
M1 Board Outline:
  the board outline again, w10
M2 Board Dimensions:
  rectangle: 125,-400 500,-275
  rectangle: 0,-275 125,-150
  lines w7: 0,-275 1000,-275 ; 125,-400 125,-150 ; 250,-400 250,-150 ; 500,-400 500,-150 ; 750,-400 750,-150 ; 0,-400 0,-150 1000,-150 1000,-400 0,-400
M5 Assembly Top:
  lines w10: -292,-1320.17 6308,-1320.17 ; -292,-1116.83 6310,-1116.83 ; -292,-913.5 -292,-1523.5 3713,-1523.5 6310,-1523.5 6310,-913.5 -291.5,-913.5 -291.5,-1523.5 1284,-1523.5 ; 2173,-1523.5 2173,-913.5 ; 3440,-1116.83 3440,-913.5 ; 4280,-1116.83 4280,-913.5 ; 4902,-1530 4902,-1327.17
  text "COMPONENTS MARKED 'DNP' SHOULD NOT BE POPULATED." at 1153.5,-318.5 h60
  text "ASSEMBLY VARIANT:" at 1153,-434 h60
  text ".VariantName" at 2189,-434 h60
  text "COMPONENTS MARKED 'DNP' SHOULD NOT BE POPULATED." at 1153.5,-708.5 h30
  text "ASSEMBLY VARIANT:" at 1153,-824 h30
  text ".VariantName" at 2189,-824 h30
  text "PCB VIEWED FROM TOP SIDE" at -228.5,-1045.67 h30
  text "BOARD #:" at 2248,-1045.67 h30
  text ".PRJ_Number" at 2793.5,-1045.67 h30
  text "REV:" at 3638,-1045.67 h30
  text ".PCB_Rev" at 3929.5,-1045.67 h30
  text "SVN REV:" at 4476,-1045.67 h30
  text ".VersionControl_RevNumber" at 4982,-1045.67 h30
  text "IGNORE ->" at -228.5,-1248.49 h30
  text "PLOT NAME =" at -228.5,-1454.34 h30
  text ".plot_File_Name" at 577,-1454.34 h30
  text "GENERATED    :" at 2250,-1454.34 h30
  text ".Print_Date" at 3119.5,-1454.34 h30
  text ".Print_Time" at 3848.5,-1454.34 h30
  text "TEXAS INSTRUMENTS" at 5113,-1454.34 h30
M6 Assembly Bottom:
  text "COMPONENTS MARKED 'DNP' SHOULD NOT BE POPULATED." at 6102,-318 h60
  text ".VariantName" at 5058,-434 h60
  text "ASSEMBLY VARIANT:" at 6097,-434 h60
M9 Title Sheet:
  drawing of 57 lines, arcs and shapes, not listed
  text "1" at 741.34,7650 h70
  text "2" at 3237,7650 h70
  text "3" at 5726.34,7650 h70
  text "4" at 8233.01,7650 h70
  text "5" at 10732,7650 h70
  text "6" at 13237,7650 h70
  text "A" at -415,6507 h70
  text "A" at 14385,6507 h70
  text "B" at -415,4127 h70
  text "B" at 14385,4127 h70
  text "C" at -415,1752 h70
  text "C" at 14385,1752 h70
  text "PROJECT TITLE:" at 11345,-109 h45
  text ".PRJ_Title" at 11395,-242.33 h70
  text "DESIGNED FOR:" at 11345,-410 h45
  text ".PRJ_Customer" at 11395,-550 h70
  text "D" at -415,-618 h70
  text "D" at 14385,-618 h70
  text "FILE NAME:" at 11345,-710 h45
  text ".PCB_File_Name_No_Path" at 11395,-830 h70
  text "Texas Instruments (TI) and/or its licensors do not warrant the accuracy or completeness of this specification" at 6375.5,-991.84 h45
  text "ENGINEER:" at 11345,-1000 h45
  text "LAYOUT BY:" at 12850,-1000 h45
  text "or any information contained therein. TI and/or its licensors do not warrant that this design will meet" at 6330.51,-1104.5 h45
  text ".PRJ_Engineer" at 11395,-1154.99 h70
  text ".PCB_Layout" at 12900.5,-1154.99 h70
  text "the specifications, will be suitable for your application or fit for any particular purpose, or will operate in" at 6330.51,-1217.17 h45
  text ".Layer_Name" at 578.5,-1244.99 h60
  text "ALTIUM DESIGNER VERSION:" at 12850,-1310 h45
  text "an implementation. TI and/or its licensors do not warrant that the design is production worthy. You should" at 6330.51,-1329.83 h45
  text "completely validate and test your design implementation to confirm the system functionality for your application." at 6375.5,-1442.5 h45
  text ".print_Scale" at 11395,-1443.33 h70
  text ".Application_BuildNumber" at 12900.5,-1443.33 h70
  text "1" at 741.34,-1650 h70
  text "2" at 3237,-1650 h70
  text "3" at 5726.34,-1650 h70
  text "4" at 8233.01,-1650 h70
  text "5" at 10732,-1650 h70
  text "6" at 13237,-1650 h70
M10 Fab Notes:
  drawing of 189 lines, arcs and shapes, not listed
  text "DESIGN INFORMATION" at 12383.02,5965.17 h60
  text "MIN. TRACK WIDTH:" at 11738.46,5833.05 h60
  text "8" at 12834.7,5833.05 h60
  text "MIL" at 12989.46,5833.05 h60
  text "MIN. CLEARANCE:" at 11738.46,5708.92 h60
  text "0.2" at 12774.7,5708.93 h60
  text "mm" at 12989.46,5708.92 h60
  text "MIN. VIA PAD SIZE:" at 11738.46,5584.8 h60
  text "24" at 12804.71,5584.8 h60
  text "MIL" at 12989.46,5584.8 h60
  text "0.05mm (2MIL)" at 12433.46,5454.9 h60
  text "MINIMUM ANNULAR RING" at 11409.23,5446.67 h60
  text "EXTERNAL" at 13141.46,5446.67 h60
  text "PER" at 11609.23,5336.55 h60
  text "IPC-D-275 CLASS 2 LEVEL C" at 11829.23,5336.54 h60
  text "MIL, HOLES" at 13317.46,5236.07 h60
  text "+/-" at 12925,5227.48 h60
  text "+/-" at 13779,5227.48 h60
  text "REGISTRATION TOLERANCES:" at 11409.23,5226.42 h60
  text "METAL" at 12609,5226.42 h60
  text "5" at 13185.2,5226.42 h60
  text "3" at 14018.2,5226.42 h60
  text "MIL" at 14134.46,5226.42 h60
  text "HOLE SIZE TOLERANCE (UNLESS OTHERWISE SPECIFIED):" at 11409.23,5128.1 h60
  text "+/-" at 13779,5125.23 h60
  text "3" at 14018.2,5124.17 h60
  text "MIL" at 14134.46,5124.17 h60
  text "MATERIAL:" at 11334.46,4986.52 h60
  text "FR-4 High Tg" at 12320.9,4858 h60
  text "X" at 12176.46,4850.01 h60
  text "FR-408" at 11755.46,4845.49 h60
  text "OTHER" at 13243.46,4845.49 h60
  text "62 MIL (1.6mm) +/-10%" at 12075.56,4702.46 h60
  text "X" at 11955.46,4700.01 h60
  text "THICKNESS:" at 11409.23,4694.24 h60
  text "OTHER" at 13360.46,4694.24 h60
  text "TOLERANCE:" at 11409.23,4555.92 h60
  text "X" at 12257.46,4555.92 h60
  text "ANSI IPC-6012 TYPE 3 CLASS 2" at 12435.48,4555.92 h60
  text "OTHER +/-" at 12435.46,4411.73 h60
  text "BOW & TWIST:" at 11409.23,4266.54 h60
  text "X" at 12257.46,4266.54 h60
  text "ANSI IPC-6012 TYPE 3 CLASS 2" at 12435.48,4266.54 h60
  text "OTHER +/-" at 12435.46,4119.85 h60
  text "DRILLING:" at 11334.46,3989.23 h60
  text "NC_DRILL FILES" at 13095.46,3884.04 h60
  text "REFERENCE:" at 11409.23,3880.1 h60
  text "X" at 12066.46,3880.01 h60
  text "AS SHOWN" at 12244.46,3880.1 h60
  text "X" at 12967.46,3880.1 h60
  text "OTHER" at 13393.46,3737.85 h60
  text "PTH COPPER THICKNESS:" at 11408.91,3734.32 h60
  text "X" at 12548.14,3734.32 h60
  text "20-30 um" at 12676.14,3734.32 h60
  text "BOARD FINISH:" at 11334.46,3586.73 h60
  text "SILKSCREEN:" at 11489.68,3476.6 h60
  text "X" at 12447.46,3476.6 h60
  text "TOP" at 12564.46,3476.6 h60
  text "X" at 12957.46,3476.6 h60
  text "BOTTOM" at 13075.46,3476.6 h60
  text "SILKSCREEN COLOR:" at 11489.68,3321.41 h60
  text "X" at 12446.46,3321.41 h60
  text "WHITE" at 12564.46,3321.41 h60
  text "OTHER" at 13075.46,3321.41 h60
  text "X" at 12577.46,3177.96 h60
  text "GREEN" at 12695.46,3177.96 h60
  text "OTHER" at 13313.46,3177.96 h60
  text "SOLDER RESIST COLOR:" at 11489.68,3171.1 h60
  text "X" at 12577.46,3023.71 h60
  text "MATTE" at 12695.46,3023.71 h60
  text "SEMI-GLOSS" at 13313,3023.07 h60
  text "IMMERSION GOLD (ENIG)" at 12395.46,2850.94 h60
  text "ENEPIG" at 13733,2843.72 h60
  text "SURFACE FINISH:" at 11334.46,2842.72 h60
  text "X" at 12217.46,2842.72 h60
  text "IMM. TIN/SILVER OR EQUIV" at 11664,2705.4 h60
  text "OTHER" at 13095.46,2701.47 h60
  text "ARRAY/PANEL:" at 11334.46,2546.09 h60
  text "CUT AND TRIM PER M1 BOARD OUTLINE" at 12395.46,2537.87 h60
  text "N.C. ROUTE" at 12395.46,2401.9 h60
  text "X" at 13083.46,2401.9 h60
  text "V. SCORE" at 13261.46,2401.9 h60
  text "CERTIFICATION:" at 11334.46,2272.77 h60
  text "MATERIALS AND WORKMANSHIP FOR ALL PCBS" at 12059.46,2272.77 h60
  text "TO MEET OR EXCEED THE REQUIREMENTS OF:" at 12059.46,2178.71 h60
  text "X" at 11696.97,2050.08 h60
  text "ANSI IPC-A-600F CLASS ->" at 11824.96,2050.08 h60
  text "X" at 13472.97,2050.08 h60
  text "2" at 13582.96,2050.08 h60
  text "1" at 13267.96,2048.58 h60
  text "3" at 13936.96,2048.58 h60
  text "X" at 12508.97,1902.39 h60
  text "RoHS" at 12636.96,1902.39 h60
  text "OTHER" at 13281.36,1902.39 h60
  text "PER ORDER" at 13678.42,1902.39 h60
  text "ALL BOARDS MUST MEET OR EXCEED UL94-V0 REQUIREMENTS." at 11362,1748.57 h60
  text "PCB MUST BEAR THE UL94V-0 UL REGISTERED MATERIAL ID NUMBER" at 11362,1632.5 h60
  text "ADDITIONAL REQUIREMENTS:" at 11334.46,1463.08 h60
  text "MICROSECTION:" at 11409.23,1355.95 h60
  text "YES" at 12314.96,1355.95 h60
  text "REQUIRED" at 13176.46,1211.62 h60
  text "BARE BOARD ELEC. TEST:" at 11409.23,1208.76 h60
  text "NONE" at 12714.96,1208.76 h60
  text "X" at 13058.46,1208.76 h60
  text "PER ORDER" at 13768.46,1208.76 h60
  text "XX MIL VIAS REQUIRE NON-CONDUCTIVE FILL AND PLANARIZE" at 11577.38,1003.82 h59
  text "XX MIL VIAS REQUIRE CONDUCTIVE FILL AND PLANARIZE" at 11585.38,899.84 h60
  text "OUTER XX MIL TRACES REQUIRE 50 OHM SINGLE-ENDED IMPEDANCE" at 11584.39,736.46 h58
  text "LAYER 2 & 3 (INNER LAYERS) XX MIL WIDE, XX MIL SPACE / TRACES REQUIRE 100 OHM DIFFERENTIAL IMPEDANCE" at 11576.39,500.74 h60
  text ".Layer_Name" at 578,-1249.49 h60
M11 Gerber Information:
  lines w10: -290.5,-1316.67 6309.5,-1316.67 ; -290.5,-1113.33 6311.5,-1113.33 ; -290.5,-910 -290.5,-1520 3714.5,-1520 6311.5,-1520 6311.5,-910 -290,-910 -290,-1520 1285.5,-1520 ; 2174.5,-1520 2174.5,-910 ; 3441.5,-1113.33 3441.5,-910 ; 4281.5,-1113.33 4281.5,-910 ; 4903.5,-1526.5 4903.5,-1323.67
  text "ALL ARTWORK VIEWED FROM TOP SIDE" at -227,-1042.17 h60
  text "BOARD #:" at 2249.5,-1042.17 h60
  text ".PRJ_Number" at 2795,-1042.17 h60
  text "REV:" at 3639.5,-1042.17 h60
  text ".PCB_Rev" at 3931,-1042.17 h60
  text "SVN REV:" at 4477.5,-1042.17 h60
  text ".VersionControl_RevNumber" at 4983.5,-1042.17 h60
  text "LAYER NAME =" at -227,-1244.99 h60
  text "TID #:" at 2249.5,-1245.5 h60
  text ".TID" at 2795,-1245.5 h60
  text "PLOT NAME =" at -227,-1450.84 h60
  text ".plot_File_Name" at 578.5,-1450.84 h60
  text "GENERATED    :" at 2251.5,-1450.84 h60
  text ".Print_Date" at 3121,-1450.84 h60
  text ".Print_Time" at 3850,-1450.84 h60
  text "TEXAS INSTRUMENTS" at 5114.5,-1450.84 h60
M12 Stackup:
  drawing of 191 lines, arcs and shapes, not listed
  text "Layer" at 9800.88,7469.68 h60
  text "Name" at 10210.79,7469.68 h60
  text "Material" at 11140.54,7469.68 h60
  text "Thickness" at 12000.3,7469.68 h60
  text "Constant" at 12650.14,7469.68 h60
  text "Board Layer Stack" at 13220,7469.68 h60
  text "1" at 9800.88,7349.68 h60
  text "Top Overlay" at 10210.79,7349.68 h60
  text "2" at 9800.88,7229.68 h60
  text "Top Solder" at 10210.79,7229.68 h60
  text "Solder Resist" at 11140.54,7229.68 h60
  text "0.40mil" at 12000.3,7229.68 h60
  text "3.5" at 12650.14,7229.68 h60
  text "3" at 9800.88,7109.68 h60
  text "Top Layer" at 10210.79,7109.68 h60
  text "Copper" at 11140.54,7109.68 h60
  text "1.40mil" at 12000.3,7109.68 h60
  text "4" at 9800.88,6989.68 h60
  text "Dielectric1" at 10210.79,6989.68 h60
  text "FR-4" at 11140.54,6989.68 h60
  text "59.20mil" at 12000.3,6989.68 h60
  text "4.8" at 12650.14,6989.68 h60
  text "5" at 9800.88,6869.68 h60
  text "Bottom Layer" at 10210.79,6869.68 h60
  text "Copper" at 11140.54,6869.68 h60
  text "1.40mil" at 12000.3,6869.68 h60
  text "6" at 9800.88,6749.68 h60
  text "Bottom Solder" at 10210.79,6749.68 h60
  text "Solder Resist" at 11140.54,6749.68 h60
  text "0.40mil" at 12000.3,6749.68 h60
  text "3.5" at 12650.14,6749.68 h60
  text "7" at 9800.88,6629.68 h60
  text "Bottom Overlay" at 10210.79,6629.68 h60
  text ".Layer_Name" at 577,-1248.49 h30
M13 Component Bodies Top:
  text ".Layer_Name" at 577,-1248.49 h30
M14 Component Bodies Bottom:
  text ".Layer_Name" at 577,-1248.49 h30
M15 Courtyards Top:
  text ".Layer_Name" at 577,-1248.49 h30
M16 Courtyards Bottom:
  text ".Layer_Name" at 577,-1248.49 h30
Drill Drawing:
  lines w10: 3486.76,146.81 3531.04,146.81 3508.9,102.53 3486.76,146.81 ; 3486.76,202.15 3531.04,202.15 3531.04,246.43 3486.76,246.43 3486.76,202.15 ; 3486.76,323.91 3508.9,301.77 3531.04,323.91 3508.9,346.05 3486.76,323.91 ; 3486.76,412.47 3497.83,412.47 3508.9,401.4 3519.97,412.47 3531.04,412.47 3519.97,423.54 3531.04,434.6 3519.97,434.6 3508.9,445.67 3497.83,434.6 3486.76,434.6 3497.83,423.54 3486.76,412.47 ; 3486.76,501.02 3486.76,512.09 3497.83,523.16 3486.76,534.23 3486.76,545.3 3497.83,545.3 3508.9,534.23 3519.97,545.3 3531.04,545.3 3531.04,534.23 3519.97,523.16 3531.04,512.09 3531.04,501.02 3519.97,501.02 3508.9,512.09 3497.83,501.02 3486.76,501.02 ; 3486.76,611.71 3497.83,611.71 3497.83,600.64 3519.97,600.64 3519.97,611.71 3531.04,611.71 3531.04,633.85 3519.97,633.85 3519.97,644.92 3497.83,644.92 3497.83,633.85 3486.76,633.85 3486.76,611.71
  lines w12: 3446,72.64 6558.94,72.64 ; 3446,670.38 6558.94,670.38 ; 3761.63,-26.98 3761.63,770 ; 4078.82,-26.98 4078.82,770 ; 4700.56,-26.98 4700.56,770 ; 4944.88,-26.98 4944.88,770 ; 5305.22,-26.98 5305.22,770 ; 6014.73,-26.98 6014.73,770 ; 3446,-26.98 6558.94,-26.98 6558.94,770 3446,770 3446,-26.98
  text "Symbol" at 3505.77,700.26 h72
  text "Quantity" at 3791.52,700.26 h72
  text "Finished Hole Size" at 4108.7,700.26 h72
  text "Plated" at 4730.45,700.26 h72
  text "Hole Type" at 4974.77,700.26 h72
  text "Drill Layer Pair" at 5335.11,700.26 h72
  text "Hole Tolerance" at 6044.62,700.26 h72
  text "26" at 3791.52,600.64 h60
  text "15.00mil (0.381mm)" at 4108.7,600.64 h60
  text "PTH" at 4730.45,600.64 h60
  text "Round" at 4974.77,600.64 h60
  text "Top Layer - Bottom Layer" at 5335.11,600.64 h60
  text "56" at 3791.52,501.02 h60
  text "16.00mil (0.406mm)" at 4108.7,501.02 h60
  text "PTH" at 4730.45,501.02 h60
  text "Round" at 4974.77,501.02 h60
  text "Top Layer - Bottom Layer" at 5335.11,501.02 h60
  text "10" at 3791.52,401.4 h60
  text "20.00mil (0.508mm)" at 4108.7,401.4 h60
  text "PTH" at 4730.45,401.4 h60
  text "Round" at 4974.77,401.4 h60
  text "Top Layer - Bottom Layer" at 5335.11,401.4 h60
  text "17" at 3791.52,301.77 h60
  text "45.28mil (1.150mm)" at 4108.7,301.77 h60
  text "PTH" at 4730.45,301.77 h60
  text "Round" at 4974.77,301.77 h60
  text "Top Layer - Bottom Layer" at 5335.11,301.77 h60
  text "4" at 3791.52,202.15 h60
  text "125.98mil (3.200mm)" at 4108.7,202.15 h60
  text "PTH" at 4730.45,202.15 h60
  text "Round" at 4974.77,202.15 h60
  text "Top Layer - Bottom Layer" at 5335.11,202.15 h60
  text "2" at 3791.52,102.53 h60
  text "188.00mil (4.775mm)" at 4108.7,102.53 h60
  text "PTH" at 4730.45,102.53 h60
  text "Round" at 4974.77,102.53 h60
  text "Top Layer - Bottom Layer" at 5335.11,102.53 h60
  text "115 Total" at 3791.52,2.91 h60
  text ".Layer_Name" at 577,-1248.49 h30

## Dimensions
0,-400 to 1000,-400 on M2 Board Dimensions
0,0 to 0,2040 on M2 Board Dimensions
0,0 to 3040,0 on M2 Board Dimensions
